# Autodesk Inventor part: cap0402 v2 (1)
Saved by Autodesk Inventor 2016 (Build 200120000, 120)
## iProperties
Created: 2016-09
Part Number: cap0402 v2 (1)
Material: Generic
Document SubType Name: Modeling
Designer: Administrator
Appearance: Generic
Author: Administrator
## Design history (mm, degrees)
feature "Body6"
feature "Body8"
feature "Body18"
body "Solid1"
body "Solid2"
body "Solid3"
